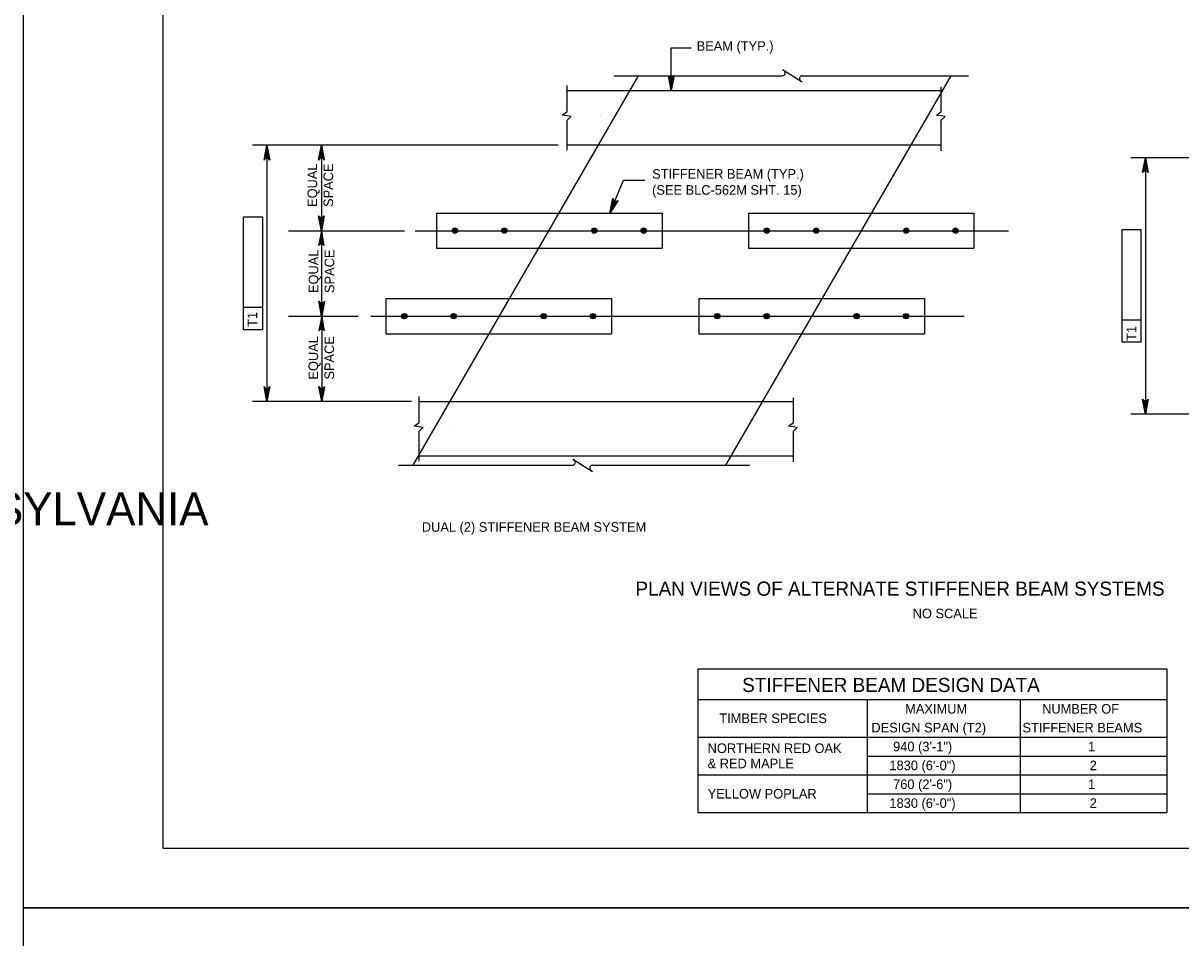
# Model space of a CAD drawing. Extents: x -13 to 81, y -176 to 0.
# Drawn here: x 34 to 48.49, y -88.38 to -76.92 of the extents above; entities that cross this region are included whole.
import ezdxf

# ---------------------------------------------------------------- set-up
doc = ezdxf.new("R2010")
doc.units = 0
for name, color, linetype in [('Level 1', 7, 'Continuous'), ('Level 10', 7, 'Continuous'), ('Level 2', 7, 'Continuous'), ('Level 3', 7, 'Continuous'), ('Level 4', 7, 'Continuous'), ('Level 63', 7, 'Continuous'), ('Level 8', 7, 'Continuous')]:
    doc.layers.add(name, color=color, linetype=linetype)

msp = doc.modelspace()

# ---------------------------------------------------------------- linework, layer by layer
at = {"layer": 'Level 1'}
msp.add_lwpolyline([(35.75, -87.25), (67.25, -87.25), (67.25, -66.75), (35.75, -66.75)], close=True, dxfattribs=at)
at = {"layer": 'Level 10'}
for p, q in [((42.445, -85.007), (42.445, -86.806)), ((42.445, -85.007), (48.311, -85.007)), ((48.311, -85.007), (48.311, -86.806)), ((42.445, -85.389), (48.311, -85.389)), ((44.564, -85.389), (44.564, -86.806)), ((46.475, -85.389), (46.475, -86.806)), ((42.445, -85.861), (48.311, -85.861)), ((44.564, -86.098), (48.311, -86.098)), ((42.445, -86.334), (48.311, -86.334)), ((44.564, -86.57), (48.311, -86.57)), ((42.445, -86.806), (48.311, -86.806))]:
    msp.add_line(p, q, dxfattribs=at)
at = {"layer": 'Level 2'}
for p, q in [((41.695, -77.578), (38.876, -82.456)), ((45.609, -77.578), (42.789, -82.456))]:
    msp.add_line(p, q, dxfattribs=at)
at = {"layer": 'Level 3'}
for p, q in [((43.503, -77.5), (43.749, -77.655)), ((41.398, -77.578), (43.5, -77.578)), ((43.749, -77.578), (45.831, -77.578)), ((40.808, -78.024), (40.808, -77.7)), ((40.808, -77.763), (45.49, -77.763)), ((45.49, -78.024), (45.49, -77.715)), ((40.746, -78.072), (40.808, -78.024)), ((40.856, -78.089), (40.746, -78.072)), ((40.808, -78.132), (40.856, -78.089)), ((45.429, -78.072), (45.49, -78.024)), ((45.539, -78.089), (45.429, -78.072)), ((45.49, -78.132), (45.539, -78.089)), ((40.808, -78.509), (40.808, -78.132)), ((45.49, -78.517), (45.49, -78.132)), ((45.49, -78.448), (40.808, -78.448)), ((39.172, -79.299), (39.172, -79.739)), ((39.172, -79.299), (41.995, -79.299)), ((41.995, -79.299), (41.995, -79.739)), ((43.076, -79.299), (43.076, -79.739)), ((43.076, -79.299), (45.899, -79.299)), ((45.899, -79.299), (45.899, -79.739)), ((40.58, -79.518), (40.58, -79.518)), ((39.172, -79.739), (41.995, -79.739)), ((43.076, -79.739), (45.899, -79.739)), ((38.54, -80.369), (41.363, -80.369)), ((38.54, -80.369), (38.54, -80.809)), ((41.363, -80.369), (41.363, -80.809)), ((42.457, -80.369), (45.279, -80.369)), ((42.457, -80.369), (42.457, -80.809)), ((45.279, -80.369), (45.279, -80.809)), ((39.948, -80.588), (39.948, -80.588)), ((38.54, -80.809), (41.363, -80.809)), ((42.457, -80.809), (45.279, -80.809)), ((38.957, -81.919), (38.957, -81.595)), ((38.957, -81.658), (43.64, -81.658)), ((43.64, -81.919), (43.64, -81.61)), ((38.895, -81.967), (38.957, -81.919)), ((39.006, -81.984), (38.895, -81.967)), ((38.957, -82.028), (39.006, -81.984)), ((43.578, -81.967), (43.64, -81.919)), ((43.688, -81.984), (43.578, -81.967)), ((43.64, -82.028), (43.688, -81.984)), ((38.957, -82.405), (38.957, -82.028)), ((43.64, -82.412), (43.64, -82.028)), ((43.64, -82.343), (38.957, -82.343)), ((40.878, -82.378), (41.124, -82.533)), ((38.696, -82.456), (40.875, -82.456)), ((41.124, -82.456), (43.09, -82.456))]:
    msp.add_line(p, q, dxfattribs=at)
for centre, radius in [((39.403, -79.519), 0.0333), ((39.403, -79.519), 0.0295), ((39.403, -79.519), 0.025), ((39.403, -79.519), 0.0167), ((39.403, -79.519), 0.00833), ((40.021, -79.519), 0.0333), ((40.021, -79.519), 0.0295), ((40.021, -79.519), 0.025), ((40.021, -79.519), 0.0167), ((40.021, -79.519), 0.00833), ((41.147, -79.519), 0.0333), ((41.147, -79.519), 0.0295), ((41.147, -79.519), 0.025), ((41.147, -79.519), 0.0167), ((41.147, -79.519), 0.00833), ((41.765, -79.519), 0.0333), ((41.765, -79.519), 0.0295), ((41.765, -79.519), 0.025), ((41.765, -79.519), 0.0167), ((41.765, -79.519), 0.00833), ((43.306, -79.519), 0.0333), ((43.306, -79.519), 0.0295), ((43.306, -79.519), 0.025), ((43.306, -79.519), 0.0167), ((43.306, -79.519), 0.00833), ((43.924, -79.519), 0.0333), ((43.924, -79.519), 0.0295), ((43.924, -79.519), 0.025), ((43.924, -79.519), 0.0167), ((43.924, -79.519), 0.00833), ((45.05, -79.519), 0.0333), ((45.05, -79.519), 0.0295), ((45.05, -79.519), 0.025), ((45.05, -79.519), 0.0167), ((45.05, -79.519), 0.00833), ((45.668, -79.519), 0.0333), ((45.668, -79.519), 0.0295), ((45.668, -79.519), 0.025), ((45.668, -79.519), 0.0167), ((45.668, -79.519), 0.00833), ((38.77, -80.589), 0.0333), ((38.77, -80.589), 0.0295), ((38.77, -80.589), 0.025), ((38.77, -80.589), 0.0167), ((38.77, -80.589), 0.00833), ((39.388, -80.589), 0.0333), ((39.388, -80.589), 0.0295), ((39.388, -80.589), 0.025), ((39.388, -80.589), 0.0167), ((39.388, -80.589), 0.00833), ((40.514, -80.589), 0.0333), ((40.514, -80.589), 0.0295), ((40.514, -80.589), 0.025), ((40.514, -80.589), 0.0167), ((40.514, -80.589), 0.00833), ((41.132, -80.589), 0.0333), ((41.132, -80.589), 0.0295), ((41.132, -80.589), 0.025), ((41.132, -80.589), 0.0167), ((41.132, -80.589), 0.00833), ((42.687, -80.589), 0.0333), ((42.687, -80.589), 0.0295), ((42.687, -80.589), 0.025), ((42.687, -80.589), 0.0167), ((42.687, -80.589), 0.00833), ((43.305, -80.589), 0.0333), ((43.305, -80.589), 0.0295), ((43.305, -80.589), 0.025), ((43.305, -80.589), 0.0167), ((43.305, -80.589), 0.00833), ((44.431, -80.589), 0.0333), ((44.431, -80.589), 0.0295), ((44.431, -80.589), 0.025), ((44.431, -80.589), 0.0167), ((44.431, -80.589), 0.00833), ((45.049, -80.589), 0.0333), ((45.049, -80.589), 0.0295), ((45.049, -80.589), 0.025), ((45.049, -80.589), 0.0167), ((45.049, -80.589), 0.00833)]:
    msp.add_circle(centre, radius, dxfattribs=at)
for centre, start, end in [((43.5, -77.541), 270, 60), ((43.752, -77.614), 95.3286, 237.8672), ((40.875, -82.419), 270, 60), ((41.127, -82.492), 95.3286, 237.8672)]:
    msp.add_arc(centre, 0.0364, start, end, dxfattribs=at)
at = {"layer": 'Level 4'}
for p, q in [((42.111, -77.229), (42.361, -77.229)), ((38.4, -78.448), (36.87, -78.448)), ((37.05, -78.448), (37.05, -81.658)), ((40.695, -78.448), (37.288, -78.448)), ((38.247, -78.448), (37.645, -78.448)), ((37.733, -78.448), (37.733, -79.518)), ((49.104, -78.605), (47.864, -78.605)), ((48.044, -78.605), (48.044, -81.815)), ((41.514, -78.886), (41.781, -78.886)), ((36.759, -79.346), (36.995, -79.346)), ((36.759, -80.758), (36.759, -79.346)), ((36.995, -79.346), (36.995, -80.758)), ((37.322, -79.518), (38.773, -79.518)), ((37.733, -79.518), (37.733, -80.47)), ((38.906, -79.518), (46.332, -79.518)), ((47.752, -79.503), (47.989, -79.503)), ((47.752, -80.616), (47.752, -79.503)), ((47.989, -79.503), (47.989, -80.915)), ((36.995, -80.482), (36.759, -80.482)), ((37.322, -80.588), (38.193, -80.588)), ((38.352, -80.589), (45.778, -80.589)), ((47.752, -80.915), (47.752, -80.616)), ((47.989, -80.639), (47.752, -80.639)), ((36.995, -80.758), (36.759, -80.758)), ((37.736, -80.706), (37.736, -81.658)), ((47.989, -80.915), (47.752, -80.915)), ((38.858, -81.658), (36.87, -81.658)), ((37.995, -81.658), (37.66, -81.658)), ((48.932, -81.815), (47.864, -81.815))]:
    msp.add_line(p, q, dxfattribs=at)
for points in [[(42.111, -77.763), (42.111, -77.229)], [(42.111, -77.763), (42.076, -77.576), (42.086, -77.591), (42.099, -77.598), (42.111, -77.6), (42.123, -77.598), (42.136, -77.591), (42.146, -77.576), (42.111, -77.763), (42.136, -77.591), (42.123, -77.598), (42.111, -77.763), (42.111, -77.6), (42.099, -77.598), (42.111, -77.763), (42.086, -77.591)], [(37.05, -78.448), (37.085, -78.634), (37.075, -78.62), (37.063, -78.612), (37.05, -78.61), (37.038, -78.612), (37.025, -78.62), (37.015, -78.634), (37.05, -78.448), (37.025, -78.62), (37.038, -78.612), (37.05, -78.448), (37.05, -78.61), (37.063, -78.612), (37.05, -78.448), (37.075, -78.62)], [(37.733, -78.448), (37.768, -78.634), (37.758, -78.62), (37.746, -78.612), (37.733, -78.61), (37.721, -78.612), (37.708, -78.62), (37.698, -78.634), (37.733, -78.448), (37.708, -78.62), (37.721, -78.612), (37.733, -78.448), (37.733, -78.61), (37.746, -78.612), (37.733, -78.448), (37.758, -78.62)], [(48.044, -78.605), (48.079, -78.791), (48.069, -78.777), (48.056, -78.769), (48.044, -78.767), (48.032, -78.769), (48.019, -78.777), (48.009, -78.791), (48.044, -78.605), (48.019, -78.777), (48.032, -78.769), (48.044, -78.605), (48.044, -78.767), (48.056, -78.769), (48.044, -78.605), (48.069, -78.777)], [(41.342, -79.299), (41.514, -78.886)], [(41.342, -79.299), (41.381, -79.113), (41.385, -79.13), (41.394, -79.142), (41.404, -79.149), (41.417, -79.151), (41.431, -79.149), (41.446, -79.14), (41.342, -79.299), (41.431, -79.149), (41.417, -79.151), (41.342, -79.299), (41.404, -79.149), (41.394, -79.142), (41.342, -79.299), (41.385, -79.13)], [(37.733, -79.518), (37.698, -79.331), (37.708, -79.346), (37.721, -79.353), (37.733, -79.355), (37.746, -79.353), (37.758, -79.346), (37.768, -79.331), (37.733, -79.518), (37.758, -79.346), (37.746, -79.353), (37.733, -79.518), (37.733, -79.355), (37.721, -79.353), (37.733, -79.518), (37.708, -79.346)], [(37.733, -79.518), (37.698, -79.704), (37.708, -79.69), (37.721, -79.682), (37.733, -79.68), (37.746, -79.682), (37.758, -79.69), (37.768, -79.704), (37.733, -79.518), (37.758, -79.69), (37.746, -79.682), (37.733, -79.518), (37.733, -79.68), (37.721, -79.682), (37.733, -79.518), (37.708, -79.69)], [(37.736, -80.588), (37.701, -80.401), (37.711, -80.416), (37.723, -80.423), (37.736, -80.425), (37.748, -80.423), (37.761, -80.416), (37.771, -80.401), (37.736, -80.588), (37.761, -80.416), (37.748, -80.423), (37.736, -80.588), (37.736, -80.425), (37.723, -80.423), (37.736, -80.588), (37.711, -80.416)], [(37.736, -80.588), (37.701, -80.774), (37.711, -80.76), (37.723, -80.752), (37.736, -80.75), (37.748, -80.752), (37.761, -80.76), (37.771, -80.774), (37.736, -80.588), (37.761, -80.76), (37.748, -80.752), (37.736, -80.588), (37.736, -80.75), (37.723, -80.752), (37.736, -80.588), (37.711, -80.76)], [(37.05, -81.658), (37.015, -81.471), (37.025, -81.486), (37.038, -81.493), (37.05, -81.495), (37.063, -81.493), (37.075, -81.486), (37.085, -81.471), (37.05, -81.658), (37.075, -81.486), (37.063, -81.493), (37.05, -81.658), (37.05, -81.495), (37.038, -81.493), (37.05, -81.658), (37.025, -81.486)], [(37.736, -81.658), (37.701, -81.471), (37.711, -81.486), (37.723, -81.493), (37.736, -81.495), (37.748, -81.493), (37.761, -81.486), (37.771, -81.471), (37.736, -81.658), (37.761, -81.486), (37.748, -81.493), (37.736, -81.658), (37.736, -81.495), (37.723, -81.493), (37.736, -81.658), (37.711, -81.486)], [(48.044, -81.815), (48.009, -81.628), (48.019, -81.643), (48.032, -81.65), (48.044, -81.652), (48.056, -81.65), (48.069, -81.643), (48.079, -81.628), (48.044, -81.815), (48.069, -81.643), (48.056, -81.65), (48.044, -81.815), (48.044, -81.652), (48.032, -81.65), (48.044, -81.815), (48.019, -81.643)]]:
    msp.add_lwpolyline(points, dxfattribs=at)
for points in [[(42.111, -77.763), (42.112, -77.758), (42.11, -77.758)], [(48.024, -78.724), (48.064, -78.724), (48.044, -78.605)], [(41.342, -79.299), (41.345, -79.295), (41.342, -79.294)], [(37.714, -80.47), (37.753, -80.47), (37.733, -80.588)], [(37.716, -80.706), (37.756, -80.706), (37.736, -80.588)], [(37.03, -81.538), (37.07, -81.538), (37.05, -81.658)], [(37.716, -81.54), (37.756, -81.54), (37.736, -81.658)], [(48.024, -81.695), (48.064, -81.695), (48.044, -81.815)]]:
    msp.add_lwpolyline(points, close=True, dxfattribs=at)
at = {"layer": 'Level 63'}
for points in [[(34, -88), (68, -88), (68, -66), (34, -66)], [(34, -110), (68, -110), (68, -88), (34, -88)]]:
    msp.add_lwpolyline(points, close=True, dxfattribs=at)
at = {"layer": 'Level 8'}
for p, q in [((41.219, -78.077), (41.219, -78.077)), ((41.219, -78.079), (41.219, -78.079)), ((40.58, -79.518), (40.58, -79.518)), ((39.948, -80.588), (39.948, -80.588)), ((39.337, -81.974), (39.337, -81.974))]:
    msp.add_line(p, q, dxfattribs=at)

# ---------------------------------------------------------------- texts
at = {"layer": 'Level 1'}
msp.add_text('COMMONWEALTH OF PENNSYLVANIA', height=0.41048, dxfattribs=at).set_placement((26.194, -83.207))
at = {"layer": 'Level 4'}
for s, height, p in [('BEAM (TYP.)', 0.12, (42.428, -77.265)), ('STIFFENER BEAM (TYP.)', 0.12, (41.871, -78.867)), ('(SEE BLC-562M SHT. 15)', 0.12, (41.871, -79.068)), ('DUAL (2) STIFFENER BEAM SYSTEM', 0.12, (38.989, -83.289)), ('PLAN VIEWS OF ALTERNATE STIFFENER BEAM SYSTEMS', 0.17717, (41.663, -84.09)), ('NO SCALE', 0.12, (45.132, -84.372)), ('STIFFENER BEAM DESIGN DATA', 0.17717, (42.998, -85.296)), ('MAXIMUM', 0.12, (45.038, -85.566)), ('NUMBER OF ', 0.12, (46.752, -85.566)), ('TIMBER SPECIES', 0.12, (42.712, -85.685)), ('DESIGN SPAN (T2)', 0.12, (44.615, -85.802)), ('STIFFENER BEAMS', 0.12, (46.506, -85.802)), ('940 (3\'-1")', 0.12, (44.887, -86.039)), ('NORTHERN RED OAK', 0.12, (42.566, -86.06)), ('1', 0.12, (47.326, -86.039)), ('& RED MAPLE', 0.12, (42.566, -86.251)), ('1830 (6\'-0")', 0.12, (44.841, -86.275)), ('2', 0.12, (47.347, -86.275)), ('760 (2\'-6")', 0.12, (44.887, -86.511)), ('1', 0.12, (47.326, -86.511)), ('YELLOW POPLAR', 0.12, (42.566, -86.63)), ('1830 (6\'-0")', 0.12, (44.841, -86.747)), ('2', 0.12, (47.347, -86.747))]:
    msp.add_text(s, height=height, dxfattribs=at).set_placement(p)
for p in [(36.929, -80.723), (47.931, -80.898)]:
    msp.add_text('T1', height=0.12, rotation=90, dxfattribs=at).set_placement(p)
at = {"layer": 'Level 8'}
for s, p in [('EQUAL ', (37.679, -79.221)), ('SPACE', (37.879, -79.221)), ('EQUAL ', (37.693, -80.299)), ('SPACE', (37.893, -80.299)), ('EQUAL ', (37.691, -81.383)), ('SPACE', (37.891, -81.383))]:
    msp.add_text(s, height=0.12, rotation=89.9708, dxfattribs=at).set_placement(p)

doc.saveas('drawing.dxf')
